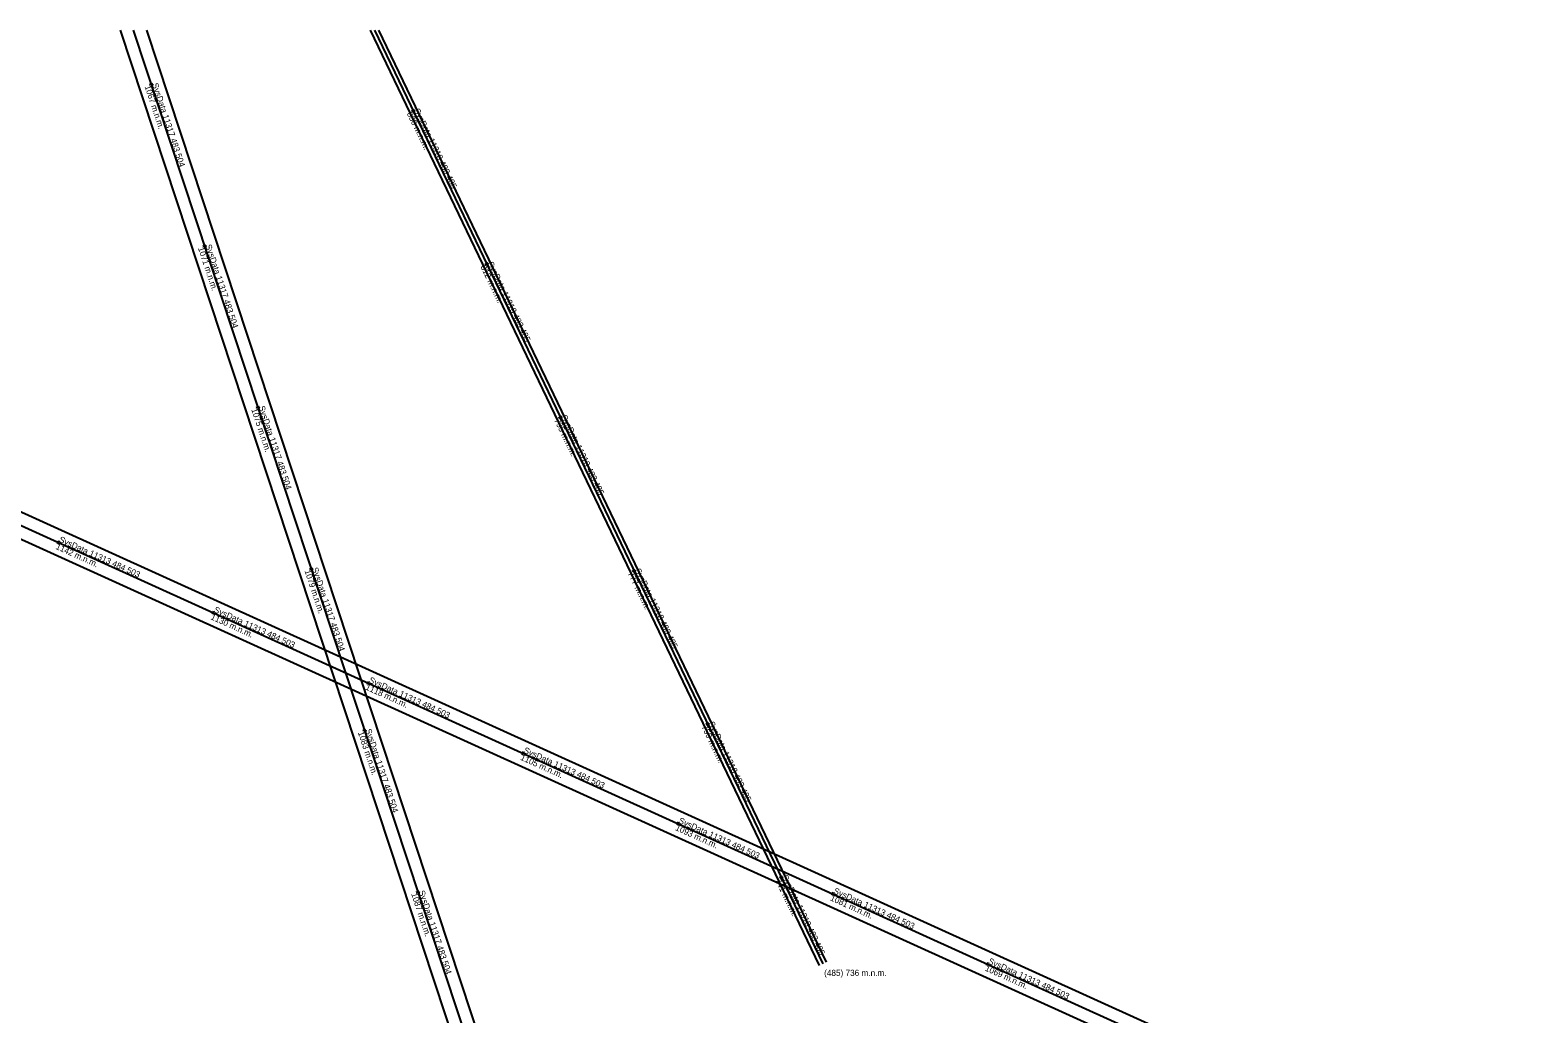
# Model space of a CAD drawing. Extents: x -651139 to -648154, y -984180 to -982978.
# Drawn here: x -650522 to -649635, y -983557 to -982978 of the extents above; entities that cross this region are included whole.
import ezdxf

# ---------------------------------------------------------------- set-up
doc = ezdxf.new("R2010")
doc.units = 0
doc.layers.add('Vrstva 1', color=7, linetype='Continuous')

msp = doc.modelspace()

# ---------------------------------------------------------------- linework, layer by layer
at = {"layer": 'Vrstva 1'}
for p, q in [((-650469.03, -982978.2), (-650072.12, -984180.43)), ((-650461.27, -982978.2), (-650064.36, -984180.43)), ((-650453.51, -982978.2), (-650056.6, -984180.43)), ((-650322.03, -982978.2), (-650057.91, -983528.17)), ((-650319.51, -982978.2), (-650055.86, -983527.19)), ((-650316.99, -982978.2), (-650053.81, -983526.21)), ((-650451.74, -983010.25), (-650449.84, -983009.63)), ((-650297.76, -983025.8), (-650295.96, -983024.94)), ((-650957.84, -983066.12), (-648502.2, -984180.43)), ((-650960.86, -983072.77), (-648519.87, -984180.43)), ((-650963.88, -983079.42), (-648537.54, -984180.43)), ((-650420.39, -983105.21), (-650418.49, -983104.59)), ((-650254.47, -983115.95), (-650252.66, -983115.08)), ((-650389.04, -983200.17), (-650387.14, -983199.54)), ((-650211.18, -983206.09), (-650209.37, -983205.22)), ((-650505.13, -983278.47), (-650505.96, -983280.29)), ((-650357.69, -983295.13), (-650355.79, -983294.5)), ((-650167.89, -983296.23), (-650166.08, -983295.37)), ((-650414.07, -983319.79), (-650414.9, -983321.61)), ((-650323.01, -983361.12), (-650323.83, -983362.94)), ((-650124.59, -983386.38), (-650122.79, -983385.51)), ((-650326.34, -983390.09), (-650324.44, -983389.46)), ((-650231.94, -983402.44), (-650232.77, -983404.26)), ((-650140.88, -983443.76), (-650141.71, -983445.58)), ((-650081.3, -983476.52), (-650079.5, -983475.66)), ((-650294.99, -983485.05), (-650293.09, -983484.42)), ((-650049.82, -983485.08), (-650050.64, -983486.9)), ((-650055.86, -983527.19), (-650055.86, -983527.19)), ((-649958.75, -983526.4), (-649959.58, -983528.23))]:
    msp.add_line(p, q, dxfattribs=at)

# ---------------------------------------------------------------- texts
for s, rotation, p in [('1067 m.n.m.', 288.27029, (-650454.66, -983011.3)), ('SysData 11317 483 504', 288.27029, (-650450.26, -983009.95)), ('830 m.n.m.', 295.65248, (-650300.51, -983027.24)), ('SysData 11318 483 485', 295.65248, (-650296.37, -983025.23)), ('1071 m.n.m.', 288.27029, (-650423.27, -983106.37)), ('SysData 11317 483 504', 288.27029, (-650418.95, -983104.79)), ('812 m.n.m.', 295.65248, (-650257.23, -983117.35)), ('SysData 11318 483 485', 295.65248, (-650253.09, -983115.35)), ('SysData 11317 483 504', 288.27029, (-650387.61, -983199.73)), ('1075 m.n.m.', 288.27029, (-650391.94, -983201.26)), ('795 m.n.m.', 295.65248, (-650213.91, -983207.55)), ('SysData 11318 483 485', 295.65248, (-650209.8, -983205.48)), ('SysData 11313 484 503', 335.59257, (-650505.29, -983278.95)), ('1142 m.n.m.', 335.59257, (-650507.19, -983283.13)), ('1079 m.n.m.', 288.27029, (-650360.61, -983296.17)), ('SysData 11317 483 504', 288.27029, (-650356.25, -983294.72)), ('777 m.n.m.', 295.65248, (-650170.66, -983297.61)), ('SysData 11318 483 485', 295.65248, (-650166.47, -983295.71)), ('1130 m.n.m.', 335.59257, (-650416.09, -983324.48)), ('SysData 11313 484 503', 335.59257, (-650414.21, -983320.28)), ('SysData 11313 484 503', 335.59257, (-650323.07, -983361.64)), ('1118 m.n.m.', 335.59257, (-650325.08, -983365.77)), ('SysData 11318 483 485', 295.65248, (-650123.22, -983385.77)), ('1083 m.n.m.', 288.27029, (-650329.22, -983391.25)), ('SysData 11317 483 504', 288.27029, (-650324.89, -983389.69)), ('759 m.n.m.', 295.65248, (-650127.33, -983387.85)), ('SysData 11313 484 503', 335.59257, (-650232.11, -983402.91)), ('1105 m.n.m.', 335.59257, (-650233.98, -983407.11)), ('1093 m.n.m.', 335.59257, (-650142.89, -983448.45)), ('SysData 11313 484 503', 335.59257, (-650140.98, -983444.26)), ('741 m.n.m.', 295.65248, (-650084.02, -983478.03)), ('SysData 11318 483 485', 295.65248, (-650079.89, -983476.01)), ('SysData 11313 484 503', 335.59257, (-650049.89, -983485.6)), ('1087 m.n.m.', 288.27029, (-650297.91, -983486.1)), ('SysData 11317 483 504', 288.27029, (-650293.53, -983484.69)), ('1081 m.n.m.', 335.59257, (-650051.82, -983489.77)), ('SysData 11313 484 503', 335.59257, (-649958.92, -983526.88)), ('(485) 736 m.n.m.', 0.037, (-650055.06, -983534.32)), ('1069 m.n.m.', 335.59257, (-649960.78, -983531.09))]:
    msp.add_text(s, height=3.6, rotation=rotation, dxfattribs=at).set_placement(p)

doc.saveas('drawing.dxf')
